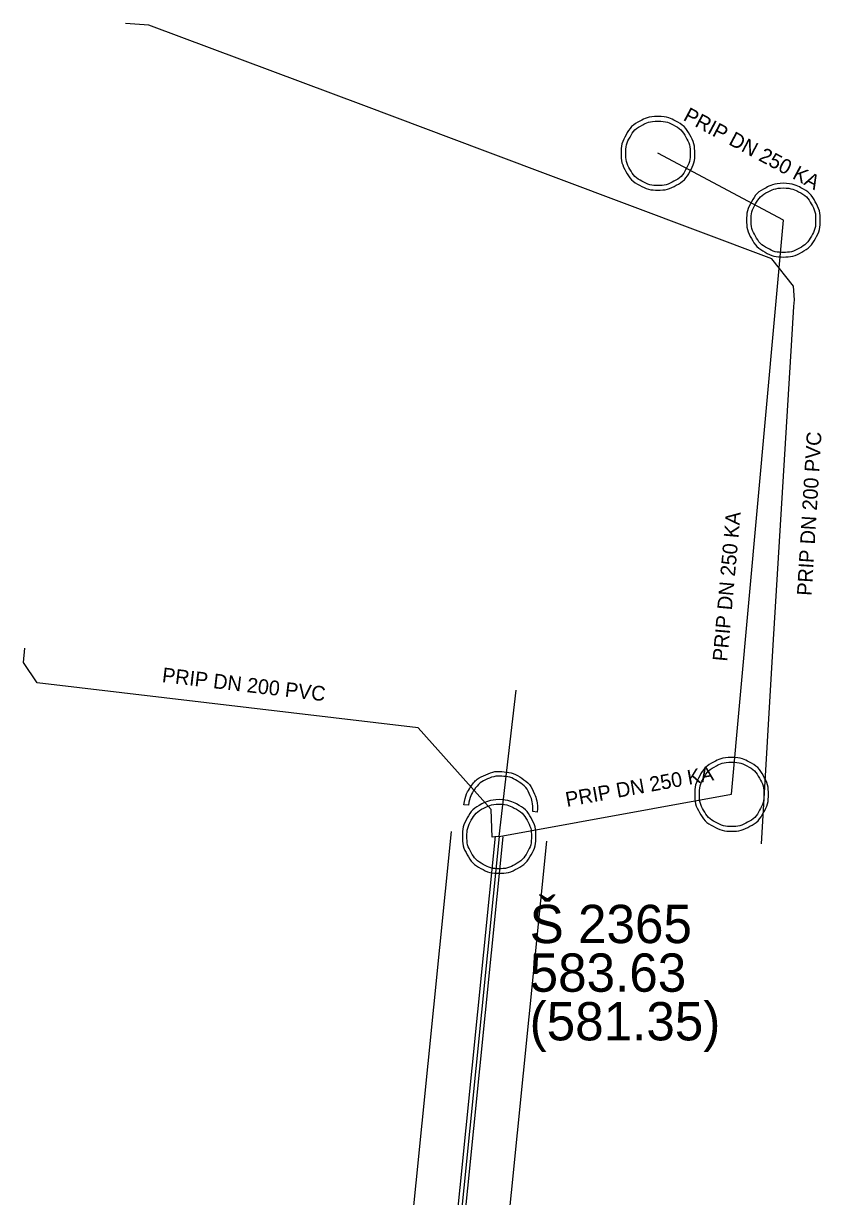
# Model space of a CAD drawing. Extents: x -643575 to -638952, y -1116425 to -1110194.
# Drawn here: x -642500.61 to -642473.52, y -1114117.81 to -1114078.01 of the extents above; entities that cross this region are included whole.
import ezdxf

# ---------------------------------------------------------------- set-up
doc = ezdxf.new("R2010")
doc.units = 0
for name, color, linetype in [('Default', 7, 'Continuous'), ('K Nepropojené křížení', 7, 'Continuous'), ('K Označení šachty', 7, 'Continuous'), ('K Popis přípojky', 7, 'Continuous'), ('K Přípojka', 7, 'Continuous'), ('K Stoka', 7, 'Continuous'), ('K Stoka - ochranné pásmo tisk', 7, 'Continuous'), ('K Stoka - okraje', 7, 'Continuous')]:
    doc.layers.add(name, color=color, linetype=linetype)

msp = doc.modelspace()

# ---------------------------------------------------------------- linework, layer by layer
at = {"layer": 'Default'}
for points in [[(-642479.071, -1114081.16), (-642478.756, -1114081.16), (-642478.457, -1114081.321), (-642478.158, -1114081.482), (-642477.989, -1114081.783), (-642477.82, -1114082.084), (-642477.82, -1114082.411), (-642477.82, -1114082.736), (-642477.985, -1114083.033), (-642478.15, -1114083.33), (-642478.447, -1114083.495), (-642478.745, -1114083.66), (-642479.071, -1114083.66), (-642479.395, -1114083.66), (-642479.693, -1114083.495), (-642479.99, -1114083.33), (-642480.155, -1114083.033), (-642480.32, -1114082.736), (-642480.32, -1114082.411), (-642480.32, -1114082.084), (-642480.152, -1114081.783), (-642479.984, -1114081.482), (-642479.686, -1114081.321), (-642479.387, -1114081.16), (-642479.071, -1114081.16)], [(-642479.07, -1114081.316), (-642479.347, -1114081.316), (-642479.609, -1114081.457), (-642479.871, -1114081.598), (-642480.017, -1114081.861), (-642480.164, -1114082.123), (-642480.164, -1114082.41), (-642480.164, -1114082.694), (-642480.019, -1114082.954), (-642479.874, -1114083.214), (-642479.614, -1114083.359), (-642479.353, -1114083.504), (-642479.07, -1114083.504), (-642478.787, -1114083.504), (-642478.526, -1114083.359), (-642478.266, -1114083.214), (-642478.121, -1114082.954), (-642477.976, -1114082.694), (-642477.976, -1114082.41), (-642477.976, -1114082.123), (-642478.125, -1114081.861), (-642478.273, -1114081.598), (-642478.534, -1114081.457), (-642478.795, -1114081.316), (-642479.07, -1114081.316)], [(-642474.811, -1114083.43), (-642474.496, -1114083.43), (-642474.197, -1114083.591), (-642473.898, -1114083.752), (-642473.729, -1114084.053), (-642473.56, -1114084.354), (-642473.56, -1114084.681), (-642473.56, -1114085.006), (-642473.725, -1114085.303), (-642473.89, -1114085.6), (-642474.187, -1114085.765), (-642474.485, -1114085.93), (-642474.811, -1114085.93), (-642475.135, -1114085.93), (-642475.433, -1114085.765), (-642475.73, -1114085.6), (-642475.895, -1114085.303), (-642476.06, -1114085.006), (-642476.06, -1114084.681), (-642476.06, -1114084.354), (-642475.892, -1114084.053), (-642475.724, -1114083.752), (-642475.426, -1114083.591), (-642475.127, -1114083.43), (-642474.811, -1114083.43)], [(-642474.81, -1114083.586), (-642475.087, -1114083.586), (-642475.349, -1114083.727), (-642475.611, -1114083.868), (-642475.757, -1114084.131), (-642475.904, -1114084.393), (-642475.904, -1114084.68), (-642475.904, -1114084.964), (-642475.759, -1114085.224), (-642475.614, -1114085.484), (-642475.354, -1114085.629), (-642475.093, -1114085.774), (-642474.81, -1114085.774), (-642474.527, -1114085.774), (-642474.266, -1114085.629), (-642474.006, -1114085.484), (-642473.861, -1114085.224), (-642473.716, -1114084.964), (-642473.716, -1114084.68), (-642473.716, -1114084.393), (-642473.865, -1114084.131), (-642474.013, -1114083.868), (-642474.274, -1114083.727), (-642474.535, -1114083.586), (-642474.81, -1114083.586)], [(-642476.571, -1114102.91), (-642476.256, -1114102.91), (-642475.957, -1114103.071), (-642475.658, -1114103.232), (-642475.489, -1114103.533), (-642475.32, -1114103.834), (-642475.32, -1114104.161), (-642475.32, -1114104.486), (-642475.485, -1114104.783), (-642475.65, -1114105.08), (-642475.947, -1114105.245), (-642476.245, -1114105.41), (-642476.571, -1114105.41), (-642476.895, -1114105.41), (-642477.193, -1114105.245), (-642477.49, -1114105.08), (-642477.655, -1114104.783), (-642477.82, -1114104.486), (-642477.82, -1114104.161), (-642477.82, -1114103.834), (-642477.652, -1114103.533), (-642477.484, -1114103.232), (-642477.186, -1114103.071), (-642476.887, -1114102.91), (-642476.571, -1114102.91)], [(-642476.57, -1114103.066), (-642476.847, -1114103.066), (-642477.109, -1114103.207), (-642477.371, -1114103.348), (-642477.517, -1114103.611), (-642477.664, -1114103.873), (-642477.664, -1114104.16), (-642477.664, -1114104.444), (-642477.519, -1114104.704), (-642477.374, -1114104.964), (-642477.114, -1114105.109), (-642476.853, -1114105.254), (-642476.57, -1114105.254), (-642476.287, -1114105.254), (-642476.026, -1114105.109), (-642475.766, -1114104.964), (-642475.621, -1114104.704), (-642475.476, -1114104.444), (-642475.476, -1114104.16), (-642475.476, -1114103.873), (-642475.625, -1114103.611), (-642475.773, -1114103.348), (-642476.034, -1114103.207), (-642476.295, -1114103.066), (-642476.57, -1114103.066)], [(-642485.655, -1114104.514), (-642485.621, -1114104.19), (-642485.426, -1114103.908), (-642485.228, -1114103.626), (-642484.915, -1114103.495), (-642484.602, -1114103.365), (-642484.288, -1114103.396), (-642483.974, -1114103.428), (-642483.693, -1114103.618), (-642483.411, -1114103.808), (-642483.274, -1114104.124), (-642483.136, -1114104.439), (-642483.168, -1114104.764)], [(-642483.323, -1114104.748), (-642483.296, -1114104.464), (-642483.416, -1114104.188), (-642483.537, -1114103.912), (-642483.783, -1114103.746), (-642484.029, -1114103.579), (-642484.303, -1114103.552), (-642484.578, -1114103.524), (-642484.852, -1114103.638), (-642485.127, -1114103.752), (-642485.299, -1114103.999), (-642485.47, -1114104.246), (-642485.5, -1114104.53)], [(-642484.461, -1114104.34), (-642484.146, -1114104.34), (-642483.847, -1114104.501), (-642483.548, -1114104.662), (-642483.379, -1114104.963), (-642483.21, -1114105.264), (-642483.21, -1114105.591), (-642483.21, -1114105.916), (-642483.375, -1114106.213), (-642483.54, -1114106.51), (-642483.837, -1114106.675), (-642484.135, -1114106.84), (-642484.461, -1114106.84), (-642484.785, -1114106.84), (-642485.083, -1114106.675), (-642485.38, -1114106.51), (-642485.545, -1114106.213), (-642485.71, -1114105.916), (-642485.71, -1114105.591), (-642485.71, -1114105.264), (-642485.542, -1114104.963), (-642485.374, -1114104.662), (-642485.076, -1114104.501), (-642484.777, -1114104.34), (-642484.461, -1114104.34)], [(-642484.46, -1114104.496), (-642484.737, -1114104.496), (-642484.999, -1114104.637), (-642485.261, -1114104.778), (-642485.407, -1114105.041), (-642485.554, -1114105.303), (-642485.554, -1114105.59), (-642485.554, -1114105.874), (-642485.409, -1114106.134), (-642485.264, -1114106.394), (-642485.004, -1114106.539), (-642484.743, -1114106.684), (-642484.46, -1114106.684), (-642484.177, -1114106.684), (-642483.916, -1114106.539), (-642483.656, -1114106.394), (-642483.511, -1114106.134), (-642483.366, -1114105.874), (-642483.366, -1114105.59), (-642483.366, -1114105.303), (-642483.515, -1114105.041), (-642483.663, -1114104.778), (-642483.924, -1114104.637), (-642484.185, -1114104.496), (-642484.46, -1114104.496)]]:
    msp.add_open_spline(points, degree=3, dxfattribs=at)
at = {"layer": 'K Nepropojené křížení'}
for points in [[(-642485.5, -1114104.53), (-642485.655, -1114104.514)], [(-642483.168, -1114104.764), (-642483.323, -1114104.748)]]:
    msp.add_lwpolyline(points, dxfattribs=at)
at = {"layer": 'K Přípojka'}
for points in [[(-642475.56, -1114105.84), (-642475.15, -1114098.91), (-642474.54, -1114088.93), (-642474.46, -1114087.61), (-642474.43, -1114087.38), (-642474.47, -1114086.92), (-642475.2, -1114085.99), (-642484.94, -1114082.34), (-642489.06, -1114080.79), (-642496.35, -1114078.06), (-642497.143, -1114078.006)], [(-642484.46, -1114105.59), (-642476.57, -1114104.16), (-642474.809, -1114084.68), (-642479.07, -1114082.41)], [(-642484.46, -1114105.59), (-642484.7, -1114105.62), (-642484.73, -1114104.68), (-642487.21, -1114101.91), (-642500.14, -1114100.38), (-642500.61, -1114099.69), (-642500.56, -1114099.2)], [(-642484.46, -1114105.59), (-642483.878, -1114100.624)]]:
    msp.add_lwpolyline(points, dxfattribs=at)
at = {"layer": 'K Stoka'}
msp.add_lwpolyline([(-642484.46, -1114105.59), (-642489.44, -1114155.07)], dxfattribs=at)
at = {"layer": 'K Stoka - ochranné pásmo tisk'}
for points in [[(-642491.057, -1114154.907), (-642486.077, -1114105.427)], [(-642487.823, -1114155.233), (-642482.843, -1114105.753)]]:
    msp.add_lwpolyline(points, dxfattribs=at)
at = {"layer": 'K Stoka - okraje'}
for points in [[(-642489.564, -1114155.057), (-642484.584, -1114105.577)], [(-642484.336, -1114105.603), (-642489.316, -1114155.083)]]:
    msp.add_lwpolyline(points, dxfattribs=at)

# ---------------------------------------------------------------- texts
at = {"layer": 'K Označení šachty'}
for s, p in [('Š 2365', (-642483.426, -1114109.21)), ('583.63', (-642483.426, -1114110.86)), ('(581.35)', (-642483.426, -1114112.51))]:
    msp.add_text(s, height=1.3, dxfattribs=at).set_placement(p)
at = {"layer": 'K Popis přípojky'}
for s, rotation, p in [('PRIP DN 250 KA', 331.9523, (-642478.243, -1114081.273)), ('PRIP DN 200 PVC', 86.5023, (-642473.854, -1114097.434)), ('PRIP DN 250 KA', 84.8354, (-642476.719, -1114099.666)), ('PRIP DN 200 PVC', 353.2516, (-642495.923, -1114100.351)), ('PRIP DN 250 KA', 10.2729, (-642482.16, -1114104.59))]:
    msp.add_text(s, height=0.5, rotation=rotation, dxfattribs=at).set_placement(p)

doc.saveas('drawing.dxf')
